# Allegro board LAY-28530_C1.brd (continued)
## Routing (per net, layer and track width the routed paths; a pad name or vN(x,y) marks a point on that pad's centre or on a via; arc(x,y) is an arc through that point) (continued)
GND_EARTH: length 133
  TOP w0.533: J2.S1 203.57,163.5 ; J2.S1 203.57,159.9 ; J2.S1 204.73,161.7 ; J2.S1 202.41,161.7 ; 190.43,159.9 J2.S2 ; J2.S2 190.43,163.5 ; J2.S2 189.27,161.7 ; J2.S2 191.58,161.7
  L2_GND w0.508: P1.9 186.5,164.04 ; P1.9 185.14,165.4 ; P1.9 185.14,162.68 ; P1.9 183.78,164.04 ; J3.S2 162.19,159.58 ; J3.S2 160.79,158.18 ; J3.S2 159.39,159.58 ; J3.S2 160.79,160.98 ; 189.27,161.7 J2.S2 ; J2.S2 191.58,161.7 ; J2.S2 190.43,163.5 ; J5.21 120.36,165.32 ; J5.21 118.94,163.9 ; J5.21 117.51,165.32 ; J5.21 118.94,166.74 ; 141.81,159.58 J3.S1 ; J3.S1 143.21,158.18 ; J3.S1 143.21,160.98 ; J3.S1 144.61,159.58 ; J24.S1 162.18,159.58 ; J24.S1 159.39,159.58 ; J24.S1 160.78,160.97 ; J24.S1 160.78,158.18 ; J4.21 93.94,166.74 ; J4.21 93.94,163.9 ; J4.21 92.51,165.32 ; J4.21 95.36,165.32 ; J24.S2 143.2,160.97 ; J24.S2 143.2,158.18 ; J24.S2 144.6,159.58 ; J24.S2 141.81,159.58 ; 110.06,163.9 J4.22 ; J4.22 111.49,165.32 ; J4.22 110.06,166.74 ; J4.22 108.64,165.32 ; J5.22 136.49,165.32 ; J5.22 135.07,163.9 ; J5.22 133.64,165.32 ; J5.22 135.07,166.74 ; P1.10 168.86,165.4 ; P1.10 168.86,162.68 ; P1.10 167.5,164.04 ; P1.10 170.22,164.04 ; 202.41,161.7 J2.S1 ; J2.S1 204.73,161.7 ; J2.S1 203.57,163.5
  L5_PWR w0.508: 202.41,161.7 J2.S1 ; J2.S1 204.73,161.7 ; J2.S1 203.57,163.5 ; P1.10 170.22,164.04 ; P1.10 168.86,162.68 ; P1.10 168.86,165.4 ; P1.10 167.5,164.04 ; 159.39,159.58 J24.S1 ; J24.S1 160.78,160.97 ; J24.S1 162.18,159.58 ; J24.S1 160.78,158.18 ; P1.9 185.14,165.4 ; P1.9 185.14,162.68 ; P1.9 183.78,164.04 ; P1.9 186.5,164.04 ; 189.27,161.7 J2.S2 ; J2.S2 191.58,161.7 ; J2.S2 190.43,163.5 ; 160.79,158.18 J3.S2 ; J3.S2 162.19,159.58 ; J3.S2 159.39,159.58 ; J3.S2 160.79,160.98
  BOTTOM w0.508: v1(100.64,165.02) 102.16,165.02 102.55,164.64 C167.2 102.55,164.26 102.19,163.9 v1(100.75,163.9) ; C169.2 116.39,161.82 ; C169.2 112.58,161.82 ; C169.2 114.48,163.01 ; C168.2 126.8,163.12 ; C168.2 125.34,161.99 ; C168.2 128.26,161.99 ; v1(188.27,160.58) 188.27,158.8 187.76,158.29 C171.2 ; C172.2 168.15,158.29 ; C172.2 166.43,159.48 ; C172.2 164.7,158.29 ; C171.2 186.37,158.29 185.98,158.67 v1(185.98,160.58) ; C171.2 v1(187.13,160.58)
  vias: v1(112.32,164.39) v1(112.71,166.93) v1(113.72,164.39) v1(114.1,167.05) v1(114.1,165.66) v1(115.25,164.39) v1(115.5,165.78) v1(115.63,167.18) v1(116.64,164.39) v1(125.53,164.26) v1(126.8,164.26) v1(128.07,164.26) v1(164.27,160.96) v1(164.27,159.81) v1(165.54,160.96) v1(165.54,159.81) v1(166.81,160.96) v1(168.2,160.96) v1(168.2,159.94)
GND_SIGNAL: length 44.6
  TOP w0.203: U1.19 84.6,148.72 83.5,147.62 R13.2 ; U1.27 87.8,151.93 v1(88.07,152.19) ; v1(85.02,153.85) 85,153.87 U1.13 ; U1.26 87.4,151.72 v1(86.92,152.19)
  TOP w0.508: C174.2 v1(82.48,160.58) ; R4.2 v1(86.04,160.58) ; T2.2 79.35,138.48 ; T2.2 79.35,135.33 ; T2.2 80.26,136.9 ; T2.2 78.43,136.9 ; R3.2 v1(84.26,160.58)
  BOTTOM w0.508: v1(89.59,151.81) 88.96,151.18 R190.2 88.96,150.04 89.59,149.4 C184.2 ; v1(84.77,151.81) 84.51,151.56 R191.2 ; C178.1 78.54,150.29 R186.1 v1(78.29,149.53) ; T1.3 79.05,133.07 ; T1.3 80.37,132.19 ; T1.3 79.05,131.32 ; C175.2 88.07,154.48 88.45,154.1 v1(88.45,153.85) ; v1(81.46,146.1) 81.59,146.23 R192.2 C181.2 79.3,147.11 78.8,147.62 v1(77.91,147.62) ; C173.2 84.77,154.1 v1(85.02,153.85) ; v1(79.18,159.18) 80,159.18 C170.2 80,157.91 v1(79.18,157.91) ; 81.34,131.34 C21.1 ; C21.1 83.24,130.15 ; C21.1 83.24,132.53 ; C21.1 85.15,131.34 ; R2.1 v1(78.67,155.75)
  vias: v1(78.67,133.78) v1(79.94,133.91) v1(81.46,134.03) v1(82.73,146.1) v1(83.37,134.16) v1(83.88,151.81) v1(84,153.85) v1(84.89,134.16) v1(86.04,151.81) v1(86.16,153.34) v1(86.42,134.16) v1(87.31,153.34) v1(89.59,153.85)
VBAT_OPT1: length 4.5
  TOP w0.254: R84.1 111.31,106.35 110.67,106.98 109.66,106.98 108.59,108.05 U10.3
2.5G_CMP_N: length 16.5
  TOP w0.104: U8.D8 v1(157.93,134.08)
  L3_INT1 w0.104: v1(157.93,134.08) 157.66,134.35 157.65,134.54 157.65,134.66 158.43,135.43 158.43,136.32 158.81,136.7 158.81,138.35 156.25,140.91 156.25,147.07 J3.15
2.5G_CMP_P: length 16.5
  TOP w0.104: U8.E8 v1(156.94,134.07)
  L3_INT1 w0.104: v1(156.94,134.07) 157.28,134.42 157.28,134.81 158.06,135.58 158.06,136.47 158.44,136.85 158.44,138.2 155.88,140.76 155.88,147.07 J3.14
2.5G_MDI0_N: length 14.9
  TOP w0.104: U8.A2 v1(150.96,138.06)
  L3_INT1 w0.104: J3.9 149.14,149.61 149.14,147.51 150.17,146.48 150.17,138.07 150.5,137.74 150.64,137.74 v1(150.96,138.06)
2.5G_MDI0_P: length 15.5
  TOP w0.104: U8.B2 v1(150.96,137.06)
  L3_INT1 w0.104: v1(150.96,137.06) 150.64,137.37 150.34,137.37 149.8,137.91 149.8,146.33 148.77,147.36 148.77,149.61 J3.8
2.5G_MDI1_N: length 18.2
  TOP w0.104: U8.A4 v1(152.96,138.06)
  L3_INT1 w0.104: v1(152.96,138.06) 152.64,137.74 152.5,137.74 151.44,138.8 151.44,143.18 151.56,143.29 151.56,150.93 150.15,152.34 150.15,152.68 150.45,152.98 J24.3 J3.3
2.5G_MDI1_P: length 18.9
  TOP w0.104: U8.B4 v1(152.96,137.06)
  L3_INT1 w0.104: v1(152.96,137.06) 152.64,137.37 152.34,137.37 151.07,138.64 151.07,143.33 151.19,143.45 151.19,150.78 149.78,152.19 149.78,152.71 149.52,152.98 J3.2
2.5G_MDI2_N: length 18.3
  TOP w0.104: U8.A6 v1(154.96,138.06)
  L3_INT1 w0.104: J3.5 J24.5 154.64,152.98 154.22,152.56 154.22,152.18 152.84,150.8 152.84,139.39 154.49,137.74 154.64,137.74 v1(154.96,138.06)
2.5G_MDI2_P: length 19.1
  TOP w0.104: U8.B6 v1(154.96,137.06)
  L3_INT1 w0.104: v1(154.96,137.06) 154.64,137.37 154.34,137.37 152.47,139.24 152.47,150.95 153.85,152.33 153.85,152.71 153.58,152.98 J3.4
2.5G_MDI3_N: length 16.2
  TOP w0.104: U8.A8 v1(156.96,138.06)
  L3_INT1 w0.104: J3.11 J24.11 155.53,150.44 155.23,150.14 155.23,149.62 153.98,148.37 153.98,144.32 154.99,143.31 154.99,139.65 156.39,138.24 156.39,137.85 156.5,137.74 156.64,137.74 v1(156.96,138.06)
2.5G_MDI3_P: length 16.8
  TOP w0.104: U8.B8 v1(156.96,137.06)
  L3_INT1 w0.104: J3.10 154.6,150.44 154.86,150.17 154.86,149.77 153.61,148.52 153.61,144.17 154.62,143.16 154.62,139.49 156.02,138.09 156.02,137.69 156.34,137.37 156.64,137.37 v1(156.96,137.06)
12: length 10.9
  TOP w0.508: D1.A 75.89,167.15 ; D1.A 73.58,167.15 ; D1.A 74.73,168.71 ; D1.A 74.73,165.59
  BOTTOM w0.508: 73.58,167.15 D1.A ; D1.A 74.73,165.59 ; D1.A 75.89,167.15 ; D1.A 74.73,168.71
  vias: v1(76.13,167.82) v1(76.13,166.29) v1(76.76,168.32) v1(76.76,166.93) v1(76.76,165.78) v1(93.66,152.19) v1(93.66,151.18) v1(94.54,152.19) v1(94.54,151.18) v1(146.61,165.91) v1(146.61,165.02) v1(147.38,165.91) v1(147.38,165.02)
34: length 10.9
  TOP w0.508: 82.47,167.15 D3.A ; D3.A 84.78,167.15 ; D3.A 83.62,165.59 ; D3.A 83.62,168.71
  BOTTOM w0.508: D3.A 84.78,167.15 ; D3.A 83.62,165.59 ; D3.A 83.62,168.71 ; D3.A 82.47,167.15
  vias: v1(85.02,167.94) v1(85.02,166.42) v1(85.65,168.45) v1(85.65,167.05) v1(85.65,165.91) v1(104.2,152.19) v1(104.2,151.31) v1(105.09,152.19) v1(105.09,151.31) v1(149.79,166.8) v1(149.79,166.04) v1(150.68,166.55) v1(151.44,166.16)
56: length 10.9
  TOP w0.508: D2.A 80.33,167.15 ; D2.A 79.18,168.71 ; D2.A 79.18,165.59 ; D2.A 78.02,167.15
  BOTTOM w0.508: 78.02,167.15 D2.A ; D2.A 79.18,165.59 ; D2.A 80.33,167.15 ; D2.A 79.18,168.71
  vias: v1(80.57,167.94) v1(80.57,166.42) v1(81.21,168.45) v1(81.21,167.05) v1(81.21,165.91) v1(93.53,157.91) v1(93.53,157.15) v1(94.42,157.91) v1(94.42,157.15) v1(152.58,166.8) v1(153.22,166.29) v1(154.11,166.8) v1(154.11,166.04)
78: length 10.9
  TOP w0.508: D4.A 87.94,168.71 ; D4.A 87.94,165.59 ; D4.A 86.79,167.15 ; D4.A 89.1,167.15
  BOTTOM w0.508: 87.94,165.59 D4.A ; D4.A 89.1,167.15 ; D4.A 87.94,168.71 ; D4.A 86.79,167.15
  vias: v1(89.34,167.82) v1(89.34,166.29) v1(89.97,168.32) v1(89.97,166.93) v1(89.97,165.78) v1(104.45,158.67) v1(104.45,157.4) v1(105.34,158.67) v1(105.34,157.4) v1(156.39,166.55) v1(156.39,165.4) v1(157.28,166.55) v1(157.28,165.4)
A23: length 14
  TOP w0.152: U27.4 v1(196.91,52.94) ; v1(197.8,63.8) 198.12,64.13 U20.1
  L3_INT1 w0.127: v1(197.8,63.8) 197.8,53.83 v1(196.91,52.94)
A24: length 29.7
  TOP w0.152: v1(176.71,63.29) 176.71,64.56 177.59,65.44 U20.56 ; U24.4 v1(196.91,56.88)
  L3_INT1 w0.127: v1(176.71,63.29) 179.38,63.29 181.79,60.88 192.08,60.88 193.1,61.9 194.75,61.9 195.51,61.14 195.51,58.28 v1(196.91,56.88)
A25: length 28.8
  TOP w0.152: U20.55 177.45,65.93 175.82,64.31 v1(175.82,63.29) ; U23.4 v1(197.03,60.82)
  L3_INT1 w0.127: v1(175.82,63.29) 176.46,63.93 179.38,63.93 182.05,61.26 191.83,61.26 192.84,62.28 195.57,62.28 v1(197.03,60.82)
ADP_12V: length 86
  TOP w0.254: U47.8 74.35,87.55 74.1,87.81 74.1,89.33 75.11,90.35 80.83,90.35 81.34,89.84 R447.1
  TOP w0.305: R447.1 82.23,89.08 84.13,87.17 97.21,87.17 100.26,90.22 100.26,93.22 99.7,93.77 R100.1
  TOP w0.508: C77.1 93.43,90.82 ; C77.1 95.49,89.71 ; C77.1 93.43,88.61 ; 92.37,102.49 Q5.4 88.76,105.84 ; R100.1 98.86,94.97 ; R100.1 98.86,92.58 ; R100.1 98.05,93.77 ; 84.64,99.4 Q6.3 ; Q6.3 84.64,103 ; Q6.3 83.53,101.2 ; Q6.3 85.74,101.2 ; R102.1 v1(77.02,96.7) ; 99.75,95.95 C80.1 ; C80.1 99.75,97.19 ; C80.1 99.13,96.57 ; C79.1 98.99,101.09 ; C79.1 98.99,97.64 ; C79.1 97.8,99.36 ; C59.1 95.49,97.46 ; C59.1 93.43,98.56 ; C59.1 93.43,96.35
  BOTTOM w0.508: v1(77.02,96.7) 91.5,96.7 v1(92.77,95.43)
AQR105_FLASH: length 349.6
  TOP w0.254: v1(97.21,14.91) 96.78,15.34 U38.28 ; L10.1 v1(140.18,139.07)
  TOP w0.305: U37.B1 v2(157.46,26.5) ; U36.B1 v2(143.49,26.5) ; 114.66,27.99 114.66,27.39 v2(115.53,26.53) U34.B1 ; U34.M9 122.35,18.1 v2(121.95,18.5) ; U35.B1 v2(129.52,26.5) ; U36.M9 150.29,18.1 v2(149.89,18.5) ; U35.M9 v2(135.92,18.5)
  TOP w0.381: U34.M9 122.35,18.1 123.37,17.08 123.37,16.56 122.74,15.92 122.74,13.26 ; v2(143.49,26.5) 142.68,27.31 142.68,27.99 ; 150.55,13.26 150.55,15.8 151.28,16.52 151.28,17.11 150.29,18.1 U36.M9 ; 142.68,27.99 133.53,27.99 133.03,28.5 128.96,28.5 ; 142.68,27.99 142.68,28.62 143.57,29.51 151.69,29.51 153.22,27.99 156.01,27.99 157.46,26.54 v2(157.46,26.5) ; 136.71,13.26 136.84,13.38 136.84,16.05 137.34,16.56 137.34,17.08 U35.M9 ; U8.J3 v1(151.94,129.09) ; U8.L16 v1(165.92,128.06) ; 128.96,28.5 128.96,27.06 v2(129.52,26.5) ; 128.96,28.5 119.06,28.5 118.17,29.39 115.75,29.39 114.66,28.29 114.66,27.99 113.47,27.99 110.8,25.32 v1(110.8,16.43) ; U8.E3 v1(151.94,133.09) ; U8.K16 v1(165.93,129.07) ; 164.38,14.67 164.38,15.65 164.65,15.92 165.03,15.92 165.28,16.18 165.28,17.08 U37.M9 v2(163.86,18.5) ; U8.K4 v1(152.95,129.07)
  TOP w0.508: R75.2 v1(175.44,124.38) ; 164.38,14.67 164.38,13.62 164.01,13.26 v1(129.98,13.26) 110.8,13.26 ; R76.2 v1(175.44,122.35)
  TOP w0.635: v1(97.21,14.91) 97.85,14.91 98.86,13.89 108.9,13.89 109.53,13.26 110.8,13.26 v1(110.8,16.43) ; v1(145.73,127.05) v1(144.07,127.05) v1(138.11,127.05) v1(137.22,127.05)
  L4_INT2 w0.635: v1(137.22,127.05) 137.22,126.29 137.72,125.78 137.72,122.35 132.52,117.14 132.52,96.95 128.96,93.39 116.13,93.39 112.58,89.84 112.58,68.76 114.61,66.72 114.61,46.02 112.32,43.74 112.32,36.62 108.01,32.31 108.01,19.23 v1(110.8,16.43)
  L5_PWR w0.127: 178.7,132.76 J7.6 ; J7.6 179.76,131.7 ; J7.6 179.76,133.83 ; J7.6 180.83,132.76
  BOTTOM w0.381: v1(151.94,133.09) 151.88,133.14 C218.2 ; v2(149.89,18.5) 149.09,17.7 C566.1 C575.1 ; C246.2 166.05,127.94 v1(165.92,128.06) ; C238.2 152.71,129.3 v1(152.95,129.07) ; 121.21,16.69 121.21,17.76 v2(121.95,18.5) ; C576.1 C567.1 135.18,17.76 v2(135.92,18.5) ; v2(163.86,18.5) 163.06,17.7 C565.1 C578.1 ; C240.2 166.06,129.21 v1(165.93,129.07) ; C245.2 152.08,128.95 v1(151.94,129.09)
  BOTTOM w0.508: U41.7 v1(145.98,134.54) ; v1(129.98,13.26) 130.61,12.62 R393.1 R392.1 ; C596.1 98.48,14.15 97.72,14.91 v1(97.21,14.91) ; R212.2 v1(148.39,130.35) ; v1(175.44,125.27) 175.06,125.65 R222.1 ; v1(148.14,137.84) C198.1 U41.8 ; U41.3 144.71,128.7 145.09,128.32 R216.2 v1(145.73,127.05)
AQR105_VA12: length 115.3
  TOP w0.127: U21.P5 v2(138.99,70.01)
  TOP w0.305: R83.2 139.88,115.24 140.26,115.62 143.95,115.62 144.07,115.75
  TOP w0.381: U8.D6 155.43,134.58 v1(154.94,134.09) ; U8.E9 v1(157.96,133.1) ; U8.E7 v1(156.93,133.08) ; U8.D4 v1(152.99,134.13) ; U8.E5 v1(153.94,133.09)
  TOP w0.508: v1(147.25,105.71) 147,105.97 147,111.81 145.98,112.82
  L3_INT1 w0.381: v1(157.96,133.1) 158.23,132.83 159.64,132.83 160.58,133.78 160.58,134.41 160.2,134.8 160.2,135.56 160.84,136.19 160.84,138.99 v1(161.09,139.24)
  L4_INT2 w0.508: v1(147.25,105.71) 148.52,104.44 148.52,88.19 144.84,84.5 142.55,84.5 v1(138.49,80.44) 138.49,74.34 138.61,74.22
  BOTTOM w0.305: C223.2 153.8,133.09 v1(153.94,133.09)
  BOTTOM w0.381: v1(154.94,134.09) 154.87,134.02 C220.2 ; C219.2 158,133.14 v1(157.96,133.1) ; 138.11,78.79 138.11,80.06 v1(138.49,80.44) ; C224.2 156.9,133.05 v1(156.93,133.08) ; C216.2 152.96,134.16 v1(152.99,134.13) ; 161.09,140.76 v1(161.09,139.24)
  BOTTOM w0.508: R227.2 R229.2 172.9,121.59 167.19,115.87 149.92,115.87 147.63,118.16 147.63,124.89 v1(147.25,125.27) v1(146.36,125.27) v1(145.47,125.27) v1(144.46,125.27) ; R209.1 149.54,131.87 148.9,131.24 148.39,131.24 v1(148.27,131.11)
AQR105_VA22: length 59.3
  TOP w0.305: R85.1 133.66,114.73 134.3,115.36 v1(137.72,115.36)
  TOP w0.381: U8.C3 v1(152.93,135.08) ; U8.A5 v1(153.96,137.1) ; U8.P4 v1(152.92,125.09) ; U8.C9 v1(158.93,135.08) ; U8.C7 v1(156.93,135.08) ; U8.R3 v1(151.96,123.1) ; U8.A3 v1(151.93,137.08) ; U8.C5 v1(154.93,135.08) ; U8.A9 v1(157.99,137.14) ; U8.A7 v1(155.97,137.12)
  TOP w0.533: C76.1 152.55,110.06 ; C76.1 151.44,108.01 ; C76.1 151.44,112.12 ; C76.1 150.34,110.06 ; 142.59,134.83 C35.1 ; C35.1 143.69,132.77 ; C35.1 143.69,136.89 ; 150.68,113.13 C58.1 ; C58.1 150.68,116.58 ; C58.1 151.87,114.86 ; 139.58,133.53 C34.1 137.85,134.72
  TOP w0.635: L12.2 v1(175.95,136.83)
  L4_INT2 w0.635: 159.31,137.97 171.13,137.97 172.27,136.83 v1(175.95,136.83)
  BOTTOM w0.305: v1(157.99,137.14) 158.04,137.19 C194.2 ; v1(153.96,137.1) 153.98,137.13 C196.2 ; v1(155.97,137.12) 156.01,137.16 C195.2 ; v1(151.93,137.08) 151.95,137.1 C197.2
  BOTTOM w0.381: C263.2 152.08,124.25 v1(152.92,125.09) ; v1(151.96,123.1) 151.95,123.1 C271.2
  BOTTOM w0.508: 156.01,135.18 156.84,135.18 v1(156.93,135.08) ; 153.98,135.18 154.84,135.18 v1(154.93,135.08) ; C207.2 v1(152.93,135.08) ; 158.04,135.18 158.84,135.18 v1(158.93,135.08)
  vias: v1(137.72,116.25) v1(138.61,116.38) v1(138.61,115.36) v1(141.41,135.81) v1(141.41,134.16) v1(141.41,132.89) v1(149.92,118.29) v1(151.31,118.29)
AQR105_VDD: length 95.8
  TOP w0.305: v1(205.8,117.4) 205.92,117.27 U9.9
  TOP w0.381: U8.L12 v1(161.89,128.03) ; U8.M9 v1(157.97,126.11) ; U8.M11 v1(160.93,126.08) ; U8.J10 v1(158.93,130.09) ; U8.N8 v1(157.93,125.08) ; U8.P11 v1(160.93,124.08) ; U8.M7 v1(156.93,126.08) ; U8.N10 v1(159.93,125.08) ; U8.L10 v1(159.93,127.08) ; U8.N6 v1(154.93,125.08) U8.P5 ; U8.P13 v1(162.93,124.08) ; U8.K11 v1(160.93,128.08) ; U8.P9 v1(158.93,124.08) ; v1(157.93,127.08) U8.L8 ; U8.L6 v1(154.97,128.04) ; U8.P7 v1(155.93,124.08) ; U8.J12 v1(160.94,130.07) ; U8.K5 v1(153.95,128.09) ; U8.N12 v1(161.93,125.08) ; U8.K7 v1(156.93,128.08) ; U8.R8 v1(157.89,124.03) ; U8.M13 v1(162.93,126.08) ; U8.J6 v1(154.96,130.06) ; U8.R12 v1(161.93,123.08) ; U8.J8 v1(156.97,130.04) ; U8.R10 v1(158.95,123.1) ; U8.K9 v1(158.93,128.08) ; U8.K13 v1(161.96,129.06)
  TOP w0.508: R82.1 v1(213.04,115.49) ; 211.38,114.09 v1(212.27,114.09)
  TOP w0.635: v1(179.63,125.78) 179.25,126.16 179.25,127.43 177.86,128.83 177.86,146.23 177.09,146.99 L8.2
  BOTTOM w0.381: v1(154.93,125.08) 154.11,124.25 C265.2 ; C248.2 161.92,128.06 v1(161.89,128.03) ; v1(158.95,123.1) 158.93,123.08 C272.2 ; v1(153.93,125.09) 153.85,125.16 C256.2 ; v1(154.96,130.06) 155,130.1 C232.2 ; C252.2 155,128.02 v1(154.97,128.04) ; v1(159.93,125.08) 159.95,125.06 C267.2 ; C231.2 157.03,130.1 v1(156.97,130.04) ; v1(160.94,130.07) 160.97,130.1 C226.2 ; v1(156.93,126.08) 156.89,126.03 156.01,126.03 ; v1(153.95,128.09) 153.85,128 C249.2 ; C260.2 162,125.14 v1(161.93,125.08) ; C243.2 158.92,128.06 v1(158.93,128.08) ; C253.2 163.01,126.16 v1(162.93,126.08) ; v1(161.93,123.08) 162.74,122.27 C270.2 ; C227.2 158.93,130.1 v1(158.93,130.09) ; C264.2 162.98,124.13 v1(162.93,124.08) ; v1(161.96,129.06) 161.98,129.08 C239.2 ; C254.2 159.95,127.06 v1(159.93,127.08) ; C242.2 160.92,128.06 v1(160.93,128.08) ; C244.2 156.92,128.06 v1(156.93,128.08)
  BOTTOM w0.508: v1(212.27,114.09) 212.4,114.09 213.04,114.73 v1(213.04,115.49) 213.67,116.13 213.67,120.06 213.04,120.7 209.99,120.7 208.72,119.43 205.8,119.43 ; 205.8,119.43 200.84,119.43 v1(198.94,121.33) ; 205.8,119.43 v1(205.8,117.4) ; C253.2 C258.2 C257.2 ; C225.2 C226.2
  vias: v1(176.71,113.46) v1(176.71,112.44) v1(176.71,111.3) v1(177.98,113.46) v1(177.98,112.44) v1(177.98,111.3) v1(179.25,113.46) v1(179.25,112.44) v1(179.25,111.3)
AQR_INT_N: length 73.1
  TOP w0.127: U21.T3 v2(137.4,71.61)
  L3_INT1 w0.127: v2(137.4,71.61) 137.41,71.61 138.23,72.44 138.23,77.9 139.12,78.79 142.17,78.79 142.93,79.55 142.93,87.17 163.76,108 163.76,112.7 169.73,118.67 v1(169.73,121.16)
  BOTTOM w0.127: v2(137.4,71.61) 137,72.01 137,73.74 138.11,74.85
  BOTTOM w0.152: R280.2 138.11,74.85 ; R228.2 v1(169.73,121.16)
AQR_LED_GRN: length 195.6
  TOP w0.152: U8.K1 149.15,128.58 145.34,132.38 145.34,136.7 143.95,138.1 v1(143.19,138.1)
  TOP w0.305: R26.1 v1(143.19,138.1)
  L4_INT2 w0.203: v1(143.19,138.1) 141.66,138.1 136.58,133.02 136.58,122.35 131.5,117.27 131.5,97.58 128.58,94.66 116.01,94.66 111.05,89.71 111.05,69.14 113.85,66.34 113.85,46.78 111.44,44.37 111.44,37.01 107.24,32.81 107.24,16.94 111.44,12.75 111.44,11.1 112.07,10.46 129.98,10.46 131.12,9.32 v1(133.91,9.32)
  BOTTOM w0.203: v1(133.91,9.32) C602.1
  BOTTOM w0.254: D14.3 133.91,7.63 v1(133.91,9.32)
AQR_LED_YEL: length 234.7
  TOP w0.152: U8.L1 v1(150.95,127.06) ; R24.1 v1(163.38,139.11)
  L3_INT1 w0.127: v1(150.95,127.06) 154,127.06 154.49,127.56 154.49,130.35 154.74,130.6 162.36,130.6 163.4,131.65 163.4,139.09 v1(163.38,139.11)
  L4_INT2 w0.203: v1(136.33,8.68) 130.87,8.68 129.6,9.95 111.94,9.95 111.05,10.84 111.05,12.49 106.86,16.69 106.86,33.07 111.05,37.26 111.05,44.5 113.47,46.91 113.47,63.93 110.67,66.72 110.67,89.96 115.82,95.11 128.4,95.11 131.12,97.84 131.12,117.4 136.2,122.48 136.2,133.27 143.31,140.38 162.11,140.38 v1(163.38,139.11)
  BOTTOM w0.203: v1(136.33,8.68) 136.33,8.94 135.82,9.45 C601.1
  BOTTOM w0.254: v1(136.33,8.68) 136.33,6.25 D14.4
AQR_SPI_CS: length 7.9
  TOP w0.152: v1(148.65,132.26) 149.28,132.26 149.51,132.02 150.99,132.02 U8.G2
  BOTTOM w0.152: v1(148.65,132.26) 148.14,132.26 147.25,131.37 U41.1 R216.1
AQR_SPI_SCLK: length 8.8
  TOP w0.152: v1(147.5,133.65) 147.5,132.38 148.31,131.58 U8.G1
  BOTTOM w0.152: U41.6 144.71,134.92 145.98,133.65 v1(147.5,133.65)
AQR_SPI_SDI: length 6.5
  TOP w0.152: U8.F1 149.72,132.58 v1(148.9,133.4)
  BOTTOM w0.152: v1(148.9,133.4) 148.52,133.02 147.76,133.02 145.98,131.24 U41.2
AQR_SPI_SDO: length 11.6
  TOP w0.152: U8.F2 150.92,133.1 150.22,133.1 149.03,134.29 147,134.29 146.49,133.78 v1(146.49,132.89)
  BOTTOM w0.152: v1(146.49,132.89) 145.47,132.89 143.44,134.92 U41.5
COP_CKSTP_OUT_N: length 13.7
  TOP w0.152: Q9.3 182.99,42.26 184.08,43.36 v1(187.51,43.36) J13.15
  BOTTOM w0.152: R366.1 v1(187.51,43.36)
COP_HRST: length 18.3
  TOP w0.152: J13.13 v1(190.05,43.36)
  BOTTOM w0.152: Q24.2 177.98,43.1 178.24,43.36 185.48,43.36 186.24,44.12 189.29,44.12 v1(190.05,43.36) R365.1
COP_SRST: length 31.8
  TOP w0.152: v1(192.59,43.36) J13.11 192.59,49.71 191.95,50.34 174.81,50.34 174.17,49.71 Q8.2
  BOTTOM w0.152: R364.1 v1(192.59,43.36)
COP_TCK: length 10.6
  TOP w0.152: J13.7 v1(197.67,43.36)
  BOTTOM w0.152: R362.1 v1(197.67,43.36) 194.06,46.96 U44.3
COP_TDI: length 15.9
  TOP w0.152: J13.3 v1(202.75,43.48)
  BOTTOM w0.152: U44.1 195.55,47.76 199.83,43.48 v1(202.75,43.48) R360.1
COP_TDO: length 17.7
  TOP w0.152: J13.1 v1(205.29,43.48)
  BOTTOM w0.152: U44.2 195.06,47.37 199.83,42.59 204.4,42.59 v1(205.29,43.48)
COP_TMS: length 9
  TOP w0.152: J13.9 v1(195.13,43.36)
  BOTTOM w0.152: R363.1 v1(195.13,43.36) 195.13,45.13 193.7,46.57 U44.4
COP_TRST: length 8.3
  TOP w0.152: Q10.2 v1(202.75,36.75) J13.4
  BOTTOM w0.152: R369.1 v1(202.75,36.75)
CPU_RST_REQ: length 111.9
  TOP w0.127: U21.F6 v2(146.2,69.21)
  TOP w0.152: Q1.2 R17.2 v1(212.91,142.8)
  L3_INT1 w0.127: v2(146.2,69.21) 146.2,69.99 146.62,70.41 147.16,70.41 147.39,70.64 147.39,71.04 147.56,71.21 150.59,71.21 155.12,75.74 155.12,80.69 160.84,86.41 160.84,87.55 188.14,114.86 188.14,122.48 201.86,136.19 201.86,140 205.42,143.56 212.15,143.56 v1(212.91,142.8)
D1_MVREF: length 100.7
  TOP w0.254: U38.31 98.32,17.61 v1(98.86,17.07)
  TOP w0.305: v1(111.82,15.29) 111.82,19.48 112.32,19.99 115.44,19.99 U34.J1 115.95,20.5 v2(116.35,20.9) ; v2(144.29,20.9) 143.89,20.5 U36.J1 142.68,19.28 142.68,14.65 v1(142.04,14.02) ; v2(130.32,20.9) 129.92,20.5 U35.J1 128.58,19.16 128.58,16.81 v1(125.79,14.02) ; 157.86,20.5 155.12,17.76 v1(155.12,14.02) ; 157.86,20.5 U37.J1 ; 157.86,20.5 v2(158.26,20.9)
  L3_INT1 w0.508: v1(111.82,15.29) 110.42,15.29 109.15,16.56 99.37,16.56 v1(98.86,17.07)
  L4_INT2 w0.305: v1(142.04,14.02) 142.04,12.37 142.17,12.24 ; v1(125.79,14.02) 125.79,12.24
  L4_INT2 w0.508: v1(111.82,15.29) 114.86,12.24 154.62,12.24 155.12,12.75 v1(155.12,14.02)
  BOTTOM w0.305: C564.1 98.35,17.83 98.86,17.32 v1(98.86,17.07)
DCDC1_3V3: length 59.6
  TOP w0.254: 85.65,45.51 86.54,45.51 87.83,46.8 U28.22
  TOP w0.508: P3.2 v1(49.68,122.38) ; P3.52 v1(49.7,145.58) ; R149.1 C106.1 85.78,43.48 ; P3.24 v1(49.68,134.38) ; P3.41 v1(54.32,141.18) ; P3.39 v1(54.29,140.38) ; R35.1 v1(116.64,136.19)
  TOP w0.533: 82.23,50.72 L19.2 ; L19.2 83.11,48.22 ; L19.2 84,50.72 ; L19.2 83.11,53.22 ; 81.5,45.17 C107.1 ; C107.1 82.61,43.11 ; C107.1 83.71,45.17 ; C107.1 82.61,47.22 ; C95.1 83.11,57.53 ; C95.1 84.31,55.8 ; C95.1 83.11,54.07 ; C95.1 81.92,55.8
  BOTTOM w0.508: v1(49.68,122.38) 49.59,122.48 C439.1 ; 118.93,127.43 118.93,134.29 117.02,136.19 v1(116.64,136.19) ; v1(54.32,141.18) 54.28,141.22 C443.1 ; 120.33,127.43 121.09,127.43 R220.1 120.83,126.67 120.33,126.67 ; C440.1 49.64,134.41 v1(49.68,134.38) ; v1(49.7,145.58) 49.69,145.59 C428.1 ; C455.1 v1(82.99,58.6) ; 120.2,125.65 R224.1 121.34,125.02 121.6,124.76
  vias: v1(79.94,58.47) v1(79.94,57.58) v1(79.94,56.56) v1(81.08,58.6) v1(81.08,57.58) v1(81.08,56.56) v1(82.1,58.6) v1(117.79,125.14) v1(117.79,124) v1(119.18,125.14) v1(119.18,124)
DCDC2_3V3: length 354.2
  TOP w0.254: U42.6 73.32,61.66 73.59,61.39 C386.2 ; v2(187.76,12.24) 188,12 U39.F5 ; U47.6 76.37,86.55 76.64,86.28 C84.2 ; C139.1 189.03,14.4 v2(188.78,14.15) ; U38.34 98.09,19.11 v1(98.35,18.84) ; U38.10 88.47,18.61 v1(88.32,18.46) ; 101.53,32.94 106.1,32.94 106.59,33.43 U29.22 ; U39.K9 186,9.71 v2(185.48,9.19) ; U38.7 88.71,20.11 v1(88.58,20.24) ; v1(90.67,14.72) 91.28,15.32 U38.17 ; U39.E6 v2(187.89,11.21) ; v1(92.64,14.65) 92.78,14.79 U38.20 ; U38.50 93.28,24.56 v1(93.4,24.69) ; v1(96.45,14.53) 96.45,14.65 96.46,14.66 96.46,15.03 96.28,15.2 U38.27 ; v2(185.98,8.68) 186.51,9.21 U39.J10 ; U38.24 94.78,15.14 v1(94.54,14.91) 94.28,15.17 U38.23 ; U48.1 v1(156.79,95.82) ; U38.12 88.87,17.61 88.45,17.19 v1(88.32,17.19) ; C138.1 v2(187.76,14.15) ; U38.55 v1(90.78,24.64) ; U22.22 91.48,65.05 v1(91.88,65.45)
  TOP w0.305: C97.1 100.4,54.54 v1(101.4,54.54) U26.14 ; U12.9 141.94,105.74 141.92,105.71 ; U20.43 177.35,71.94 v1(177.35,71.93) ; 143.44,105.71 143.45,105.72 U12.12 ; v1(179.9,86.14) 179.76,86.28 C609.1 ; U43.1 67.23,79.05 v1(67.49,78.79) ; U43.15 58.96,79.7 58.73,79.93 C469.1 ; U21.M8 v2(141.4,67.61) ; U21.N8 v2(139.8,67.61) ; 137.85,105.71 137.84,105.73 U11.14 ; U43.10 58.6,82.95 58.45,83.11 C477.1 57.97,83.49 58.09,83.6 U43.9 ; U12.14 144.44,105.6 144.46,105.59 ; U38.37 98.47,20.61 v1(98.61,20.75) ; U11.12 136.84,105.72 136.84,105.71 ; U38.40 v1(98.32,22.11) ; U26.12 v1(101.41,55.54)
  TOP w0.381: U10.8 107.29,113.67 v1(106.74,114.22) 106.74,115.11 ; v2(192.08,14.02) 192.33,14.27 192.33,21 191.05,22.28 U33.16 ; v1(175.82,149.15) 175.69,149.28 U2.16 ; R291.1 v1(179,91.74) ; 178.11,22.28 178.86,22.28 181.79,19.35 v1(181.79,13.64) ; v1(113.34,110.41) 113.51,110.58 U13.8 113.51,113.8 C286.1 ; C157.1 v1(182.81,9.07) ; C163.2 v1(182.81,7.8) ; R86.1 v1(108.13,117.02)
  TOP w0.508: R8.1 v1(207.7,151.18) ; R167.2 v1(88.96,27.35) ; R15.2 203.64,143.56 v1(203,142.92) ; v1(178.75,88.95) 177.48,90.22 Q7.1 ; R152.1 C109.1 109.02,34.59 106.23,31.8 102.93,31.8 102.55,31.42 ; C477.1 v1(56.95,83.11) ; v1(195.89,142.8) 195.64,142.54 R23.2 ; C84.2 77.4,81.96 72.45,77.01 v1(67.62,77.01) ; C386.2 v1(74.1,60.63) ; v1(156.14,72.82) 156.14,72.95 155.5,73.58 155.5,82.73 v1(159.7,86.92) ; v1(204.91,149.27) C6.1 205.73,149.21 U3.4 ; R119.2 v1(89.34,76.25) ; R451.1 v1(63.68,63.04) ; 203.76,23.04 v1(204.65,23.04) ; R125.2 v1(89.34,74.6) ; C469.1 v1(57.08,79.93) ; R118.1 v1(90.1,77.65) ; R120.1 v1(90.1,75.74) ; U14.2 v1(198.94,105.71)
  L4_INT2 w0.762: v1(206.69,45.77) 197.29,45.77 v1(193.22,49.83) 193.22,55.93 184.71,64.44 182.94,64.44 177.35,70.03 v1(177.35,71.93) 176.46,71.93 175.7,72.69 175.7,85.77 174.55,86.92 v1(171.89,86.92)
  L5_PWR w0.508: J19.3 137.94,99.49 ; J19.3 137.09,98.64 ; J19.3 137.09,100.34 ; D17.A 141.6,3 ; D17.A 139.32,3 ; D17.A 140.46,1.86 ; D17.A 140.46,4.15 ; 147.32,3 D16.A ; D16.A 149.6,3 ; D16.A 148.46,1.86 ; D16.A 148.46,4.15 ; D15.A 165.6,3 ; D15.A 164.46,1.86 ; D15.A 163.32,3 ; D15.A 164.46,4.15
  BOTTOM w0.254: v2(187.89,11.21) 188.4,11.72 188.4,13.76 v2(188.78,14.15) ; v1(193.22,49.83) 193.06,49.67 U44.16 ; v2(187.76,12.24) v2(187.76,14.15)
  BOTTOM w0.305: R395.1 120.73,11.73 120.4,11.4 v1(120.4,6.14) ; U15.16 v1(179.9,86.14)
  BOTTOM w0.381: v1(182.81,7.8) 185.1,7.8 v2(185.98,8.68) ; C332.1 v1(177.35,71.93) ; v2(185.48,9.19) 185.35,9.07 v1(182.81,9.07) ; C182.2 v1(175.82,149.15)
  BOTTOM w0.508: C292.1 v1(123.75,84.88) ; C284.1 v1(143.95,105.2) ; C544.1 100.13,20.75 v1(98.61,20.75) 98.48,20.62 C545.1 ; 99.89,125.13 R226.1 99.89,123.38 ; v1(98.32,22.11) 98.1,21.89 C534.1 ; R264.1 v1(119.69,80.06) R265.1 ; C525.1 90.48,24.34 v1(90.78,24.64) ; v1(110.8,4.49) 111.44,5.13 R401.1 ; v1(88.14,84.25) L25.1 v1(86.92,83.36) ; v1(94.8,14.15) C598.1 ; v1(154.49,6.4) 154.49,8.18 155,8.68 R400.1 ; C558.1 88.58,18.72 v1(88.32,18.46) 88.19,18.34 C563.1 ; L27.2 156.37,72.59 v1(156.14,72.82) ; C611.1 100.56,54.2 100.89,54.53 101.39,54.53 v1(101.4,54.54) ; C581.1 94.16,15.29 v1(94.54,14.91) ; C283.1 137.22,105.33 v1(137.09,105.2) ; C285.1 v1(198.94,105.71) ; C294.1 C295.1 v1(125.28,85.01) ; C556.1 v1(99.24,18.84) ; v1(206.69,45.77) 206.18,46.28 R360.2 ; C579.1 87.69,16.56 v1(88.32,17.19) 88.58,17.45 C570.1 ; C582.1 v1(92.64,14.65) C592.1 ; C583.1 90.61,14.78 v1(90.67,14.72) ; C551.1 88.45,20.11 v1(88.58,20.24) C550.1 ; v1(91.88,65.45) 91.5,65.83 C370.1 ; v1(98.35,18.84) C557.1 ; R260.1 v1(119.69,81.2) R259.1 ; 99.62,125.91 R221.1 ; C580.1 v1(96.45,14.53) ; C293.1 v1(128.33,85.01) ; R466.2 v1(159.57,93.14) ; v1(156.79,95.82) 156.77,95.81 C646.1 ; v1(95.05,72.82) 95.94,71.93 L26.2 96.65,71.24 96.45,71.04 95.31,71.04 v1(93.78,72.57) ; R198.2 v1(189.29,142.92) ; C524.1 v1(93.4,24.69)
  BOTTOM w0.635: v1(206.69,45.77) 206.69,42.47 203.89,39.67 R369.2 R370.1 199.19,39.67 198.3,40.56 R362.2 R363.2 R364.2 R365.2 R366.2
  vias: v1(97.34,28.24) v1(98.35,28.37) v1(99.12,27.73) v1(100.13,27.73) v1(100.13,26.85) v1(101.15,26.85) v1(102.04,122.6) v1(102.29,26.85) v1(102.8,122.6) v1(103.43,122.22) v1(124.01,81.84) v1(124.01,80.44) v1(138.11,105.2) v1(142.17,105.2) v1(143.06,105.2) v1(171.89,88.19)
DCDC2_3V3_PG: length 32.2
  TOP w0.254: U38.56 90.28,24.25 90.1,24.43 R167.1 v1(88.96,25.83) ; U29.23 107.09,36.53 v1(108.01,35.61)
  BOTTOM w0.254: v1(108.01,35.61) 101.4,29 92.13,29 v1(88.96,25.83)
DCDC_1V0: length 65
  TOP w0.254: R444.2 v1(78.8,62.66)
  TOP w0.305: v2(138.19,62.01) 138.6,62.41 U21.R14 ; U21.N10 v2(139.8,66.01) ; U21.P11 v2(138.99,65.21) ; U21.M11 v2(141.4,65.21) ; U21.P9 v2(138.99,66.81) ; U21.R12 v2(138.19,64.41) ; v2(143,62.81) 142.6,63.21 U21.K13 ; v2(143.8,62.01) 143.4,62.41 U21.J14 ; v2(142.2,64.41) 141.8,64.01 U21.L12 ; U21.J12 v2(143.8,64.41) ; U21.K9 v2(143,66.81) ; U21.N12 140.2,64.01 v2(139.8,64.41) ; v2(138.99,62.81) 139.4,63.21 U21.P13 ; v2(142.2,62.01) 141.8,62.41 U21.L14 ; U21.J10 v2(143.8,66.01) ; U21.M13 141,63.21 v2(141.4,62.81) ; U21.R10 v2(138.19,66.01) ; U21.M9 v2(141.4,66.81) ; U21.L10 v2(142.2,66.01) ; v2(139.8,62.01) 140.2,62.41 U21.N14 ; U21.K11 v2(143,65.21) ; U21.T9 v2(137.4,66.81)
  BOTTOM w0.127: C397.1 137.98,64.41 v2(138.19,64.41)
  BOTTOM w0.203: C345.1 141.4,66.86 v2(141.4,66.81)
  BOTTOM w0.254: v1(78.8,62.66) 78.16,63.29 78.16,64.44 81.72,67.99 103.18,67.99 107.75,63.42 107.75,62.02 108.13,61.64 R326.2 ; v2(141.4,62.81) 141.28,62.92 C399.1 ; v2(143,62.81) 143,63.23 143.36,63.6 C398.1
  BOTTOM w0.305: v2(138.99,62.81) 138.87,62.94 C400.1 ; C341.1 122.32,68.97 v1(122.23,68.88) ; v1(125.79,60.63) 125.53,60.37 C441.1 ; C380.1 139.84,65.96 v2(139.8,66.01)
  BOTTOM w0.508: v1(157.28,68.88) 157.66,68.5 L28.2 ; C367.1 v1(121.85,64.69) ; C410.1 124.01,63.29 124.52,63.8 v1(124.52,64.69) ; C369.1 v1(117.91,64.82) ; C368.1 v1(119.82,64.82)
  vias: v1(110.17,62.66) v1(110.17,61.77) v1(110.17,60.88) v1(110.17,59.99) v1(111.18,62.66) v1(111.18,61.77) v1(111.18,60.88) v1(111.18,59.99)
DCDC_1V0_SUP: length 75.4
  TOP w0.254: v1(78.8,64.31) R445.2 77.78,65.07 77.4,65.45 71.94,65.45 71.18,64.69 71.18,62.91 71.43,62.66 U42.8
  TOP w0.508: C87.1 94.42,68.25 R127.1 96.58,68.25 97.59,67.23 97.59,64.06 98.1,63.55 99.12,63.55
  TOP w0.533: 106.23,60.36 C93.1 105.48,59.48 ; L18.2 96.92,58.47 ; L18.2 94.42,59.36 ; L18.2 94.42,57.58 ; L18.2 91.92,58.47 ; 89.46,57.02 C94.1 ; C94.1 89.46,59.41 ; C94.1 87.74,58.21 ; C94.1 91.19,58.21 ; C90.1 102.76,60.85 ; C90.1 101.66,62.91 ; C90.1 100.55,60.85 ; C90.1 101.66,58.79
  BOTTOM w0.254: R326.1 106.74,61.64 107.12,62.02 107.12,63.17 102.93,67.36 81.84,67.36 v1(78.8,64.31)
  vias: v1(103.69,62.66) v1(103.69,61.9) v1(103.69,61.14) v1(104.45,62.66) v1(104.58,61.52)
DCDC_5V0: length 26.1
  TOP w0.254: v1(190.18,132.26) 190.52,132.6 U7.11
  TOP w0.406: 186.24,140.18 C15.1 ; C15.1 186.24,143.63 ; C15.1 187.43,141.91 ; C10.1 187.43,145.46 ; C10.1 186.24,143.74 ; C10.1 186.24,147.19 ; 189.46,146.51 U4.1 188.77,146.08 ; L11.2 188.14,138.71 ; L11.2 185.98,139.57 ; L11.2 185.98,137.85 ; L11.2 183.83,138.71
  L4_INT2 w0.381: v1(190.18,132.26) 189.29,132.26 188.52,133.02 v1(188.52,139.75)
DDR4_A0: length 135.2
  TOP w0.127: v2(131.95,18.5) 131.55,18.9 131.52,18.9 U35.L3 ; v2(145.89,18.5) 145.49,18.9 U36.L3 ; U34.L3 117.55,18.9 v2(117.95,18.5) ; v2(159.86,18.5) 159.46,18.9 U37.L3
  TOP w0.178: U21.AC22 132.17,55.98 132.17,53.48 v1(133.79,51.86)
  L4_INT2 w0.127: 115.3,17.7 117.15,17.7 v2(117.95,18.5) 118.39,18.5 119.06,17.83 131.25,17.83 131.92,18.5 v2(131.95,18.5) 132.74,18.5 133.41,17.83 145.22,17.83 v2(145.89,18.5) 146.69,17.7 159.06,17.7 v2(159.86,18.5) 160.93,18.5 161.73,17.7 167.57,17.7 v1(167.7,17.57)
  L4_INT2 w0.178: 115.3,17.7 114.99,17.7 112.2,20.5 112.2,29.64 117.91,35.35 124.64,35.35 127.44,38.15 135.18,38.15 135.82,38.78 135.82,41.4 136,41.58 136.28,41.58 136.45,41.4 136.45,38.96 136.63,38.78 136.91,38.78 137.09,38.96 137.09,41.4 137.27,41.58 137.55,41.58 137.72,41.4 137.72,38.96 137.9,38.78 138.18,38.78 138.36,38.96 138.36,42.85 137.98,43.23 134.55,43.23 133.28,44.5 133.28,51.36 v1(133.79,51.86)
  BOTTOM w0.152: v1(167.7,17.57) 168.2,17.07 168.84,17.07 R386.2
DDR4_A1: length 132.7
  TOP w0.127: v2(134.2,58.81) 134.6,58.41 U21.Y19 ; U34.L7 120.75,18.9 v2(120.35,18.5) ; U35.L7 134.72,18.87 v2(134.35,18.5) ; U37.L7 162.66,18.9 v2(162.26,18.5) ; U36.L7 148.69,18.9 v2(148.29,18.5)
  TOP w0.152: R176.2 v1(168.59,18.59)
  L3_INT1 w0.127: v1(168.59,18.59) 168.08,18.08 167.44,18.08 166.93,17.57 163.25,17.57 162.33,18.5 v2(162.26,18.5) 161.46,17.7 149.15,17.7 148.36,18.5 v2(148.29,18.5) 147.49,17.7 135.18,17.7 134.39,18.5 v2(134.35,18.5) 134.32,18.5 133.52,17.7 121.21,17.7 120.42,18.5 v2(120.35,18.5) 119.55,17.7 114.23,17.7 ; v2(134.2,58.81) 134.6,58.41 134.6,56.74
  L3_INT1 w0.178: 114.23,17.7 110.8,21.13 110.8,31.93 112.17,33.29 112.17,34.25 111.99,34.42 111.71,34.42 111.54,34.25 111.54,33.37 111.36,33.2 111.11,33.2 110.93,33.37 110.93,38.53 115.25,42.85 119.69,42.85 123.12,46.28 123.12,46.53 122.93,46.72 122.68,46.72 119.31,43.35 119.06,43.35 118.8,43.61 118.8,43.86 122.23,47.29 124.26,47.29 132.01,55.04 132.01,55.67 132.39,56.06 133.91,56.06 134.6,56.74
DDR4_A2: length 142.9
  TOP w0.127: 159.31,16.43 159.31,16.56 159.95,17.19 159.95,17.61 159.46,18.1 U37.M3 ; v2(135.8,56.41) 136.2,56.81 U21.V21 ; 131.25,16.43 131.89,17.07 131.89,17.73 131.52,18.1 U35.M3 ; 117.66,16.43 117.66,16.81 118.04,17.19 118.04,17.61 117.55,18.1 U34.M3 ; U36.M3 145.49,18.1 145.98,17.61 145.98,17.19 145.6,16.81 145.6,16.43
  TOP w0.152: 159.31,16.43 v1(159.31,15.8) ; 131.25,16.43 v1(131.25,15.92) ; v1(117.15,15.92) 117.66,16.43 ; 145.6,16.43 v1(145.09,15.92)
  L4_INT2 w0.127: v1(117.15,15.92) 117.66,15.42 118.17,15.42 118.8,16.05 131.12,16.05 v1(131.25,15.92) 131.76,15.42 132.39,15.42 133.03,16.05 144.96,16.05 v1(145.09,15.92) 145.6,15.42 146.23,15.42 146.87,16.05 159.19,16.05 159.31,15.92 v1(159.31,15.8) 159.81,16.29 162.76,16.29 163,16.05 165.79,16.05 v1(167.7,14.15)
  L4_INT2 w0.178: v1(117.15,15.92) 114.74,15.92 110.67,19.99 110.67,30.4 117.15,36.88 124.14,36.88 128.28,41.02 128.28,46.23 128.45,46.4 128.63,46.4 128.81,46.23 128.81,42.01 128.99,41.83 129.17,41.83 129.34,42.01 129.34,46.61 129.52,46.78 129.77,46.78 129.95,46.61 129.95,43.53 130.13,43.36 130.31,43.36 130.49,43.53 130.49,51.48 133.53,54.53 134.42,54.53 135.31,55.42 135.31,55.93 v2(135.8,56.41)
  BOTTOM w0.152: R389.2 168.84,14.65 168.2,14.65 v1(167.7,14.15)
DDR4_A3: length 147.4
  TOP w0.127: 148.65,16.56 147.88,17.32 147.88,18.89 148.69,19.7 U36.K7 ; U37.K7 162.66,19.7 161.85,18.89 161.85,16.43 ; U34.K7 120.75,19.7 119.94,18.89 119.94,18.21 120.33,17.83 120.33,16.43 ; U35.K7 134.72,19.7 133.91,18.89 133.91,18.08 134.3,17.7 134.3,16.43
  TOP w0.152: v1(135.31,15.03) 134.3,16.05 134.3,16.43 ; v1(162.87,15.16) 161.85,16.18 161.85,16.43 ; U21.U17 137,60.01 v2(136.6,59.61) ; v1(149.03,15.03) 148.65,15.42 148.65,16.56 ; 120.33,16.43 120.33,15.67 v1(120.96,15.03) ; R182.2 v1(168.59,13.13)
  L3_INT1 w0.127: 131.52,60.01 131.52,60.01 136.2,60.01 v2(136.6,59.61) ; v1(168.59,13.13) 168.08,13.64 167.32,13.64 166.3,14.65 163.38,14.65 v1(162.87,15.16) 162.24,14.53 158.04,14.53 157.66,14.91 154.23,14.91 154.11,14.78 154.11,14.65 153.98,14.53 153.6,14.53 153.47,14.65 153.47,14.78 153.35,14.91 152.2,14.91 151.82,14.53 149.54,14.53 v1(149.03,15.03) 148.52,14.53 146.11,14.53 145.98,14.4 145.98,14.27 145.85,14.15 145.6,14.15 145.47,14.27 145.47,14.4 145.34,14.53 135.82,14.53 v1(135.31,15.03) 134.8,14.53 121.47,14.53 v1(120.96,15.03)
  L3_INT1 w0.178: 131.52,60.01 131.39,60.01 128.07,56.69 127.69,56.69 127.56,56.56 127.56,55.93 127.44,55.8 127.06,55.8 126.93,55.93 126.93,56.31 126.8,56.44 126.42,56.44 126.29,56.31 126.29,56.06 126.17,55.93 125.91,55.93 125.79,56.06 125.79,56.56 125.66,56.69 125.28,56.69 108.9,40.31 108.9,19.61 113.98,14.53 120.45,14.53 v1(120.96,15.03)
DDR4_A4: length 142.8
  TOP w0.127: v2(118.42,16.86) 118.42,18.83 117.55,19.7 U34.K3 ; v2(146.25,16.9) 146.36,17.01 146.36,18.83 145.49,19.7 U36.K3 ; U37.K3 159.46,19.7 160.33,18.83 160.33,16.94 v2(160.08,16.69) ; U35.K3 131.52,19.7 132.39,18.83 132.39,16.94 132.28,16.83 v2(132.26,16.83)
  TOP w0.152: v2(133.4,57.21) 133.8,57.61 U21.AA20 ; R178.2 v1(168.59,16.56)
  L3_INT1 w0.127: v2(133.4,57.21) 132.9,57.71 132.39,57.71 132.07,57.39 ; v2(118.42,16.86) 120.91,16.86 121.34,16.43 126.55,16.43 126.55,16.43 126.68,16.56 126.68,16.69 126.8,16.81 127.06,16.81 127.18,16.69 127.18,16.56 127.31,16.43 131.37,16.43 131.76,16.81 132.25,16.81 v2(132.26,16.83) 132.28,16.81 132.52,16.81 132.9,16.43 145.78,16.43 v2(146.25,16.9) 149.07,16.9 149.54,16.43 154.36,16.43 154.49,16.56 154.49,16.69 154.62,16.81 154.87,16.81 155,16.69 155,16.56 155.12,16.43 159.82,16.43 v2(160.08,16.69) 160.2,16.81 162.87,16.81 163.25,16.43 166.68,16.43 167.06,16.05 168.08,16.05 v1(168.59,16.56)
  L3_INT1 w0.178: 132.07,57.39 128.71,54.02 127.18,54.02 122.87,49.71 120.83,49.71 115.88,44.75 115.88,44.5 116.07,44.31 116.32,44.31 121.03,49.01 121.28,49.01 121.47,48.81 121.47,48.56 116.77,43.86 114.74,43.86 110.04,39.16 110.04,20.37 113.98,16.43 117.99,16.43 v2(118.42,16.86)
DDR4_A5: length 132
  TOP w0.127: v2(163.06,19.3) 163.46,18.9 U37.L8 ; v2(121.15,19.3) 121.55,18.9 U34.L8 ; v2(135.12,19.3) 135.52,18.9 U35.L8 ; v2(149.09,19.3) 149.49,18.9 U36.L8 ; v2(135.8,57.21) 135.4,57.61 U21.W20
  TOP w0.152: R174.2 v1(168.59,20.62)
  L3_INT1 w0.127: v1(168.59,20.62) 168.46,20.62 167.95,20.11 166.3,20.11 165.08,18.9 163.58,18.9 163.18,19.3 v2(163.06,19.3) 162.63,19.73 156.85,19.73 156.01,18.9 149.54,18.9 149.13,19.3 v2(149.09,19.3) 149.09,19.29 146.05,19.29 145.6,18.84 145.31,18.84 145.26,18.9 144.93,18.9 144.87,18.84 144.51,18.84 144.46,18.9 144.13,18.9 144.07,18.84 143.71,18.84 143.66,18.9 U35.L8 v2(135.12,19.3) 132.59,19.3 132.19,18.9 124.82,18.9 124.64,18.72 124.64,18.59 124.52,18.46 124.26,18.46 124.14,18.59 124.14,18.79 124.03,18.9 121.56,18.9 v2(121.15,19.3) 118.88,19.3 118.48,18.9 114.43,18.9 ; 136.2,55.16 136.2,56.81 v2(135.8,57.21)
  L3_INT1 w0.178: 114.43,18.9 111.56,21.77 111.56,31.16 115.55,35.15 115.55,35.3 115.37,35.48 115.04,35.48 114.86,35.66 114.86,35.94 115.04,36.12 116.47,36.12 116.64,36.29 116.64,36.57 116.47,36.75 114.85,36.75 114.74,36.87 114.74,37.51 113.34,38.91 113.34,39.29 113.53,39.48 113.78,39.48 115.94,37.32 117.72,37.32 119.44,39.04 119.44,40.82 126.04,47.42 128.45,47.42 131.44,50.41 131.44,50.66 130.99,51.1 130.74,51.1 128.45,48.81 128.2,48.81 128.01,49.01 128.01,49.26 133.41,54.66 135.69,54.66 136.2,55.16
DDR4_A6: length 136
  TOP w0.127: U21.V19 136.2,58.41 v2(135.8,58.81) ; U37.L2 158.66,18.9 v2(159.08,19.31) ; U34.L2 116.75,18.9 v2(117.15,19.3) ; v2(131.12,19.3) 130.72,18.9 U35.L2 ; U36.L2 144.69,18.9 v2(145.09,19.3)
  L4_INT2 w0.127: 138.18,54.86 138.59,55.28 138.59,57.37 138.36,57.61 136.43,57.61 136.32,57.61 136.2,57.73 U21.V19 v2(135.8,58.81) ; 115.21,18.9 116.75,18.9 v2(117.15,19.3) 117.19,19.26 120.29,19.26 120.65,18.9 124.84,18.9 125.02,18.72 125.02,18.59 125.15,18.46 125.41,18.46 125.53,18.59 125.53,18.72 125.72,18.9 130.72,18.9 v2(131.12,19.3) 131.16,19.26 133.37,19.26 133.73,18.9 143.66,18.9 143.71,18.84 144.07,18.84 144.13,18.9 144.69,18.9 v2(145.09,19.3) 145.13,19.26 148.1,19.26 148.46,18.9 155.07,18.9 155.25,18.72 155.25,18.59 155.38,18.46 155.76,18.46 155.89,18.59 155.89,18.72 156.07,18.9 158.66,18.9 v2(159.08,19.31) 162.15,19.31 162.56,18.9 166.48,18.9 v1(166.81,19.23)
  L4_INT2 w0.178: 138.18,54.86 134.17,50.85 134.17,45.39 135.31,44.24 138.74,44.24 139.5,43.48 139.5,37.89 139.25,37.64 137.47,37.64 135.69,35.86 128.38,35.86 128.2,36.04 128.2,36.32 128.38,36.5 130.18,36.5 130.36,36.68 130.36,36.95 130.18,37.13 127.69,37.13 124.9,34.34 118.42,34.34 113.21,29.13 113.21,20.75 115.06,18.9 115.21,18.9
  BOTTOM w0.152: v1(166.81,19.23) 166.93,19.1 167.29,19.1 167.43,19.24 167.97,19.24 168.11,19.1 168.84,19.1 R384.2
DDR4_A7: length 132.6
  TOP w0.127: v2(121.15,18.5) 121.55,18.1 U34.M8 ; U37.M8 163.46,18.1 v2(163.06,18.5)
  TOP w0.152: v2(136.6,57.21) 137,57.61 U21.U20 ; U35.M8 135.52,18.1 135.18,18.44 135.18,18.46 v2(135.15,18.5) ; U36.M8 149.49,18.1 v2(149.09,18.5) ; R175.2 v1(168.59,19.61)
  L3_INT1 w0.127: v1(168.59,19.61) 168.08,19.1 167.44,19.1 166.17,17.83 163.51,17.83 163.06,18.27 v2(163.06,18.5) 162.84,18.5 162.49,18.85 162.36,18.97 161.35,18.97 160.47,18.1 U36.M8 v2(149.09,18.5) 148.62,18.97 147.25,18.97 146.38,18.1 135.55,18.1 v2(135.15,18.5) 134.68,18.97 133.15,18.97 132.28,18.1 U34.M8 v2(121.15,18.5) 120.7,18.95 120.05,18.95 119.06,17.96 114.61,17.96 114.47,18.1 ; v2(136.6,57.21) 136.2,57.61 135.96,57.61 135.63,57.61 135.4,57.37 135.4,56.01
  L3_INT1 w0.178: 135.4,56.01 134.55,55.17 133.03,55.17 120.2,42.34 115.63,42.34 111.56,38.28 111.56,35.15 111.74,34.97 111.99,34.97 112.17,35.15 112.17,38.11 112.35,38.29 112.63,38.29 112.81,38.11 112.81,34.92 113.01,34.72 113.29,34.72 113.47,34.9 113.47,37.46 113.65,37.64 113.93,37.64 114.1,37.46 114.1,34.47 111.18,31.54 111.18,21.38 114.47,18.1
DDR4_A8: length 136.5
  TOP w0.122: v2(159.06,18.5) 158.66,18.1 U37.M2
  TOP w0.127: U35.M2 130.72,18.1 v2(131.12,18.5) ; v2(137.4,57.21) 137.8,57.61 U21.T20
  TOP w0.152: U36.M2 144.69,18.1 v2(145.09,18.5) ; U34.M2 116.75,18.1 v2(117.15,18.5)
  L4_INT2 w0.127: v1(167.7,18.59) 167.19,18.08 161.98,18.08 161.09,18.97 159.53,18.97 v2(159.06,18.5) 158.64,18.08 148.01,18.08 147.2,18.9 145.49,18.9 v2(145.09,18.5) U36.M2 133.65,18.1 132.77,18.97 131.59,18.97 v2(131.12,18.5) U35.M2 119.55,18.1 118.67,18.97 117.62,18.97 v2(117.15,18.5) 116.73,18.08 115.25,18.08 ; 137.8,55.11 137.8,56.81 v2(137.4,57.21)
  L4_INT2 w0.178: 115.25,18.08 112.71,20.62 112.71,29.39 118.17,34.85 124.77,34.85 127.56,37.64 135.26,37.64 135.44,37.46 135.44,37.18 135.26,37.01 131.81,37.01 131.63,36.83 131.63,36.55 131.81,36.37 135.44,36.37 137.22,38.15 138.61,38.15 138.99,38.53 138.99,43.1 138.36,43.74 134.93,43.74 133.79,44.88 133.79,51.1 137.8,55.11
  BOTTOM w0.152: v1(167.7,18.59) 168.2,18.08 168.84,18.08 R385.2
DDR4_A9: length 140.9
  TOP w0.127: v2(137.4,56.41) 137.8,56.81 U21.T21 ; 135.09,16.53 135.09,17.73 134.72,18.1 U35.M7 ; U37.M7 162.66,18.1 163.09,17.67 163.09,16.43 ; 149.12,16.46 149.12,17.67 148.69,18.1 U36.M7 ; U34.M7 120.75,18.1 121.15,17.7 121.15,16.76
  TOP w0.152: 163.09,16.43 163.09,15.7 v1(163.63,15.16) ; 121.15,16.76 121.15,15.73 v1(121.85,15.03) ; 149.12,16.46 149.12,15.83 v1(149.92,15.03) ; v1(136.07,15.03) 135.09,16.02 135.09,16.53
  L4_INT2 w0.127: v1(121.85,15.03) 128.33,15.03 128.83,14.53 135.57,14.53 v1(136.07,15.03) 136.58,15.03 136.71,14.91 136.71,14.78 136.84,14.65 137.09,14.65 137.22,14.78 137.22,14.91 137.34,15.03 144.58,15.03 145.09,14.53 149.41,14.53 v1(149.92,15.03) 150.55,15.03 150.68,14.91 150.68,14.65 150.81,14.53 151.06,14.53 151.19,14.65 151.19,14.91 151.31,15.03 158.17,15.03 158.55,14.65 163.12,14.65 v1(163.63,15.16) 164.01,15.16 164.52,14.65 166.17,14.65 v1(167.7,13.13) ; v2(137.4,56.41) 136.99,56.82 136.77,56.82 136.76,56.81 134.42,56.81 134.04,56.44
  L4_INT2 w0.178: v1(121.85,15.03) 121.34,14.53 114.74,14.53 109.66,19.61 109.66,30.91 114.36,35.61 114.36,40.94 115.75,42.34 123.5,42.34 123.88,41.96 123.88,40.87 124.06,40.69 124.47,40.69 124.64,40.87 124.64,42.21 126.04,43.61 126.8,43.61 127.06,43.86 127.06,47.17 127.56,47.67 127.56,48.44 127.95,48.82 129.09,48.82 129.47,49.2 129.47,53.26 132.39,56.18 133.79,56.18 134.04,56.44
  BOTTOM w0.152: R391.2 168.84,13.64 168.2,13.64 v1(167.7,13.13)
DDR4_A10: length 149.8
  TOP w0.127: U36.J3 145.49,20.5 146.74,19.25 146.74,16.56 146.61,16.43 ; v2(133.4,58.01) 133.8,58.41 U21.AA19 ; U35.J3 131.52,20.5 132.77,19.25 132.77,16.56 132.64,16.43 ; 118.67,16.43 118.93,16.69 118.93,17.7 118.8,17.83 118.8,19.25 117.55,20.5 U34.J3 ; U37.J3 159.46,20.5 160.71,19.25 160.71,16.43
  TOP w0.152: v1(145.98,15.92) 146.11,15.92 146.61,16.43 ; v1(132.14,15.92) 132.64,16.43 ; v1(118.04,15.92) 118.17,15.92 118.67,16.43 ; 160.71,16.43 v1(160.08,15.8) ; R180.2 v1(168.59,15.16)
  L3_INT1 w0.127: v1(168.59,15.16) 168.08,15.67 166.81,15.67 166.43,16.05 163.12,16.05 162.74,16.43 160.71,16.43 v1(160.08,15.8) 159.57,15.29 158.55,15.29 157.79,16.05 146.11,16.05 v1(145.98,15.92) 145.47,15.42 144.33,15.42 143.69,16.05 132.39,16.05 132.26,15.92 v1(132.14,15.92) 131.63,15.42 130.87,15.42 130.23,16.05 125.02,16.05 124.9,15.92 124.9,15.8 124.77,15.67 124.39,15.67 124.26,15.8 124.26,15.92 124.14,16.05 118.17,16.05 v1(118.04,15.92)
  L3_INT1 w0.178: v2(133.4,58.01) 131.93,58.01 128.58,54.66 124.9,54.66 121.47,51.23 121.47,50.98 121.73,50.72 121.97,50.72 125.22,53.96 125.59,53.96 125.79,53.77 125.79,53.52 122.48,50.21 120.33,50.21 109.66,39.55 109.66,20.11 114.48,15.29 117.4,15.29 v1(118.04,15.92)
DDR4_A11: length 137.7
  TOP w0.127: U35.N2 130.72,17.3 v2(130.32,16.9) ; U21.U21 137,56.81 v2(136.6,56.41) ; v2(158.26,16.9) 158.66,17.3 U37.N2 ; v2(144.29,16.9) 144.69,17.3 U36.N2 ; U34.N2 116.75,17.3 v2(116.35,16.9)
  L4_INT2 w0.127: v1(167.7,15.16) 166.43,16.43 163.25,16.43 162.6,17.08 159.84,17.08 159.19,16.43 158.81,16.43 158.34,16.9 v2(158.26,16.9) 157.79,16.43 156.52,16.43 156.39,16.56 156.39,16.69 156.27,16.81 156.01,16.81 155.89,16.69 155.89,16.56 155.76,16.43 144.76,16.43 v2(144.29,16.9) 143.82,16.43 130.79,16.43 v2(130.32,16.9) 129.85,16.43 127.31,16.43 127.18,16.56 127.18,16.69 127.06,16.81 126.68,16.81 126.55,16.69 126.55,16.56 126.42,16.43 116.82,16.43 v2(116.35,16.9) ; v2(136.6,56.41) 136.2,56.01 136.2,54.91
  L4_INT2 w0.178: v2(116.35,16.9) 115.88,16.43 114.99,16.43 111.18,20.24 111.18,30.15 117.4,36.37 124.39,36.37 127.18,39.16 128.45,39.16 128.68,39.39 128.68,40.64 128.86,40.82 129.04,40.82 129.22,40.64 129.22,39.34 129.39,39.16 129.62,39.16 129.8,39.34 129.8,41.4 129.98,41.58 130.16,41.58 130.33,41.4 130.33,39.34 130.51,39.16 130.69,39.16 130.87,39.34 130.87,41.58 130.48,41.96 130.48,42.21 130.74,42.47 130.99,42.47 131.95,41.51 132.2,41.51 132.39,41.71 132.39,41.96 131.25,43.1 131.25,43.35 131.5,43.61 131.75,43.61 133.22,42.15 133.47,42.15 133.66,42.34 133.66,42.59 132.26,43.99 132.26,44.37 132.14,44.5 131.37,44.5 131.25,44.63 131.25,45.01 131.37,45.13 132.14,45.13 132.26,45.26 132.26,45.77 131.12,46.91 131.12,50.72 133.15,52.75 134.04,52.75 136.2,54.91
  BOTTOM w0.152: v1(167.7,15.16) 168.2,15.67 168.84,15.67 R388.2
DDR4_A12: length 132.4
  TOP w0.127: U35.J7 134.72,20.5 v2(135.12,20.9) ; U21.U19 137,58.41 v2(136.6,58.01) ; U36.J7 148.69,20.5 v2(149.09,20.9) ; U37.J7 162.66,20.5 v2(163.06,20.9) ; v2(121.15,20.9) 120.75,20.5 U34.J7
  TOP w0.152: R171.2 v1(168.59,22.65)
  L3_INT1 w0.127: v2(136.6,58.01) 137,57.61 137,55.2 ; v1(168.59,22.65) 168.08,22.15 167.06,22.15 165.03,20.11 163.89,20.11 163.1,20.9 v2(163.06,20.9) 162.39,20.9 161.73,20.24 149.79,20.24 149.13,20.9 v2(149.09,20.9) 147.91,20.9 147.12,20.11 135.94,20.11 135.14,20.91 v2(135.12,20.9) 134.34,20.11 122.1,20.11 121.32,20.9 v2(121.15,20.9) 120.24,19.99 114.61,19.99 114.48,20.11
  L3_INT1 w0.178: 137,55.2 135.95,54.15 135.69,54.15 135.49,53.95 135.49,52.73 135.31,52.55 135.13,52.55 134.96,52.73 134.96,53.97 134.78,54.15 134.6,54.15 134.42,53.97 134.42,53.01 134.17,52.75 133.15,52.75 132.64,52.25 132.64,49.96 128.71,46.02 128.71,45.79 128.89,45.62 130.31,45.62 130.49,45.44 130.49,45.26 130.31,45.08 128.12,45.08 127.95,44.9 127.95,44.68 128.12,44.5 129.8,44.5 129.98,44.32 129.98,44.04 129.8,43.86 126.85,43.86 126.68,43.69 126.68,43.51 126.85,43.33 128.78,43.33 128.96,43.15 128.96,42.9 128.78,42.72 126.47,42.72 126.29,42.54 126.29,42.36 126.47,42.19 127.51,42.19 127.69,42.01 127.69,41.76 127.51,41.58 124.01,41.58 123.88,41.45 123.88,39.29 122.61,38.02 119.94,38.02 112.32,30.4 112.32,22.27 114.48,20.11
DDR4_A13: length 130.9
  TOP w0.127: U35.N8 135.52,17.3 v2(135.92,16.9) ; v2(134.2,57.21) 134.6,56.81 U21.Y21 ; U34.N8 121.55,17.3 v2(121.95,16.9) ; U36.N8 149.49,17.3 v2(149.89,16.9) ; v2(163.86,16.9) 163.46,17.3 U37.N8
  TOP w0.152: R177.2 v1(168.59,17.57)
  L3_INT1 w0.127: v1(168.59,17.57) 168.08,17.07 165.66,17.07 165.41,17.32 164.27,17.32 163.86,16.91 v2(163.86,16.9) 163.29,16.9 162.89,17.3 153.98,17.3 153.85,17.17 153.85,17.07 153.73,16.94 153.35,16.94 153.22,17.07 153.22,17.19 153.11,17.3 150.29,17.3 v2(149.89,16.9) 149.47,17.32 136.34,17.32 v2(135.92,16.9) 135.52,17.3 125.91,17.3 125.79,17.17 125.79,16.94 125.66,16.81 125.41,16.81 125.28,16.94 125.28,17.19 125.17,17.3 122.35,17.3 v2(121.95,16.9) 121.55,17.3 113.87,17.3
  L3_INT1 w0.178: 113.87,17.3 110.42,20.75 110.42,38.78 114.99,43.36 117.28,43.36 121.72,47.8 123.63,47.8 128.39,52.57 128.39,52.81 128.2,53.01 127.95,53.01 123.31,48.37 122.93,48.37 122.74,48.56 122.74,48.81 127.44,53.52 129.22,53.52 132.14,56.44 133.42,56.44 v2(134.2,57.21)
DDR4_A14/WE: length 136.7
  TOP w0.127: U34.H2 116.75,21.3 v2(117.15,21.7) ; 131.5,57.71 131.82,58.03 132.61,58.03 U21.AB19 ; v2(131.12,21.7) 130.72,21.3 U35.H2 ; U36.H2 144.69,21.3 v2(145.09,21.7) ; v2(159.08,21.71) 158.66,21.3 U37.H2
  TOP w0.178: v1(136.45,46.4) 135.18,46.4 130.61,50.98 130.61,56.82 131.5,57.71
  L4_INT2 w0.127: v1(167.7,23.67) 165.32,21.3 162.7,21.3 162.29,21.71 v2(159.08,21.71) 158.66,21.3 152.58,21.3 152.46,21.43 152.46,21.51 152.33,21.64 151.95,21.64 151.83,21.52 151.83,21.39 151.74,21.3 148.48,21.3 148.08,21.7 v2(145.09,21.7) 144.69,21.3 134.38,21.3 133.98,21.7 v2(131.12,21.7) 130.72,21.3 126.74,21.3 126.68,21.23 126.68,21 126.55,20.88 126.04,20.88 125.91,21 125.91,21.13 125.74,21.3 120.54,21.3 120.17,21.67 117.18,21.67 v2(117.15,21.7) 116.75,21.3 115.39,21.3 115.04,21.64 115.04,27.4
  L4_INT2 w0.178: v1(136.45,46.4) 141.03,46.4 141.53,45.9 141.53,36.12 141.03,35.61 138.49,35.61 136.71,33.83 132.64,33.83 128.2,29.39 119.74,29.39 119.56,29.56 119.56,29.74 119.74,29.92 123.2,29.92 123.37,30.1 123.37,30.27 123.2,30.45 118.09,30.45 115.04,27.4
  BOTTOM w0.152: R378.2 168.84,23.16 168.2,23.16 v1(167.7,23.67)
DDR4_ACT_N: length 136
  TOP w0.127: v2(138.19,58.01) 138.6,58.41 U21.R19 ; v2(131.89,20.9) 131.52,21.27 U35.H3 ; U36.H3 145.49,21.3 v2(145.89,20.9) ; U34.H3 117.55,21.3 v2(117.95,20.9) ; v2(159.86,20.9) 159.46,21.3 U37.H3
  L4_INT2 w0.127: 114.43,20.8 115.12,20.11 117.17,20.11 v2(117.95,20.9) 118.78,20.9 118.93,20.75 118.93,20.62 119.06,20.5 119.31,20.5 119.44,20.62 119.44,20.77 119.56,20.9 119.8,20.9 120.58,20.11 131.14,20.11 131.89,20.87 v2(131.89,20.9) 133.51,20.9 134.3,20.11 145.11,20.11 v2(145.89,20.9) 147.48,20.9 148.27,20.11 158.81,20.11 158.93,20.24 159.2,20.24 v2(159.86,20.9) 161.58,20.9 162.36,20.11 166.17,20.11 v1(167.7,21.64) ; 139.38,54.89 139.38,55.43 139.39,55.44 139.39,57.37 139.16,57.61 138.83,57.61 138.6,57.84 138.43,58.01 v2(138.19,58.01)
  L4_INT2 w0.178: 114.43,20.8 114.1,21.13 114.1,28.37 118.8,33.07 125.1,33.07 125.28,32.89 125.28,32.61 125.1,32.43 122.03,32.43 121.85,32.26 121.85,31.98 122.03,31.8 128.96,31.8 132.01,34.85 136.07,34.85 137.85,36.62 140.01,36.62 140.52,37.13 140.52,44.5 139.76,45.26 135.82,45.26 135.31,45.77 135.31,50.47 138.3,53.45 138.3,53.81 139.38,54.89
  BOTTOM w0.152: v1(167.7,21.64) 168.2,21.13 168.84,21.13 R382.2
